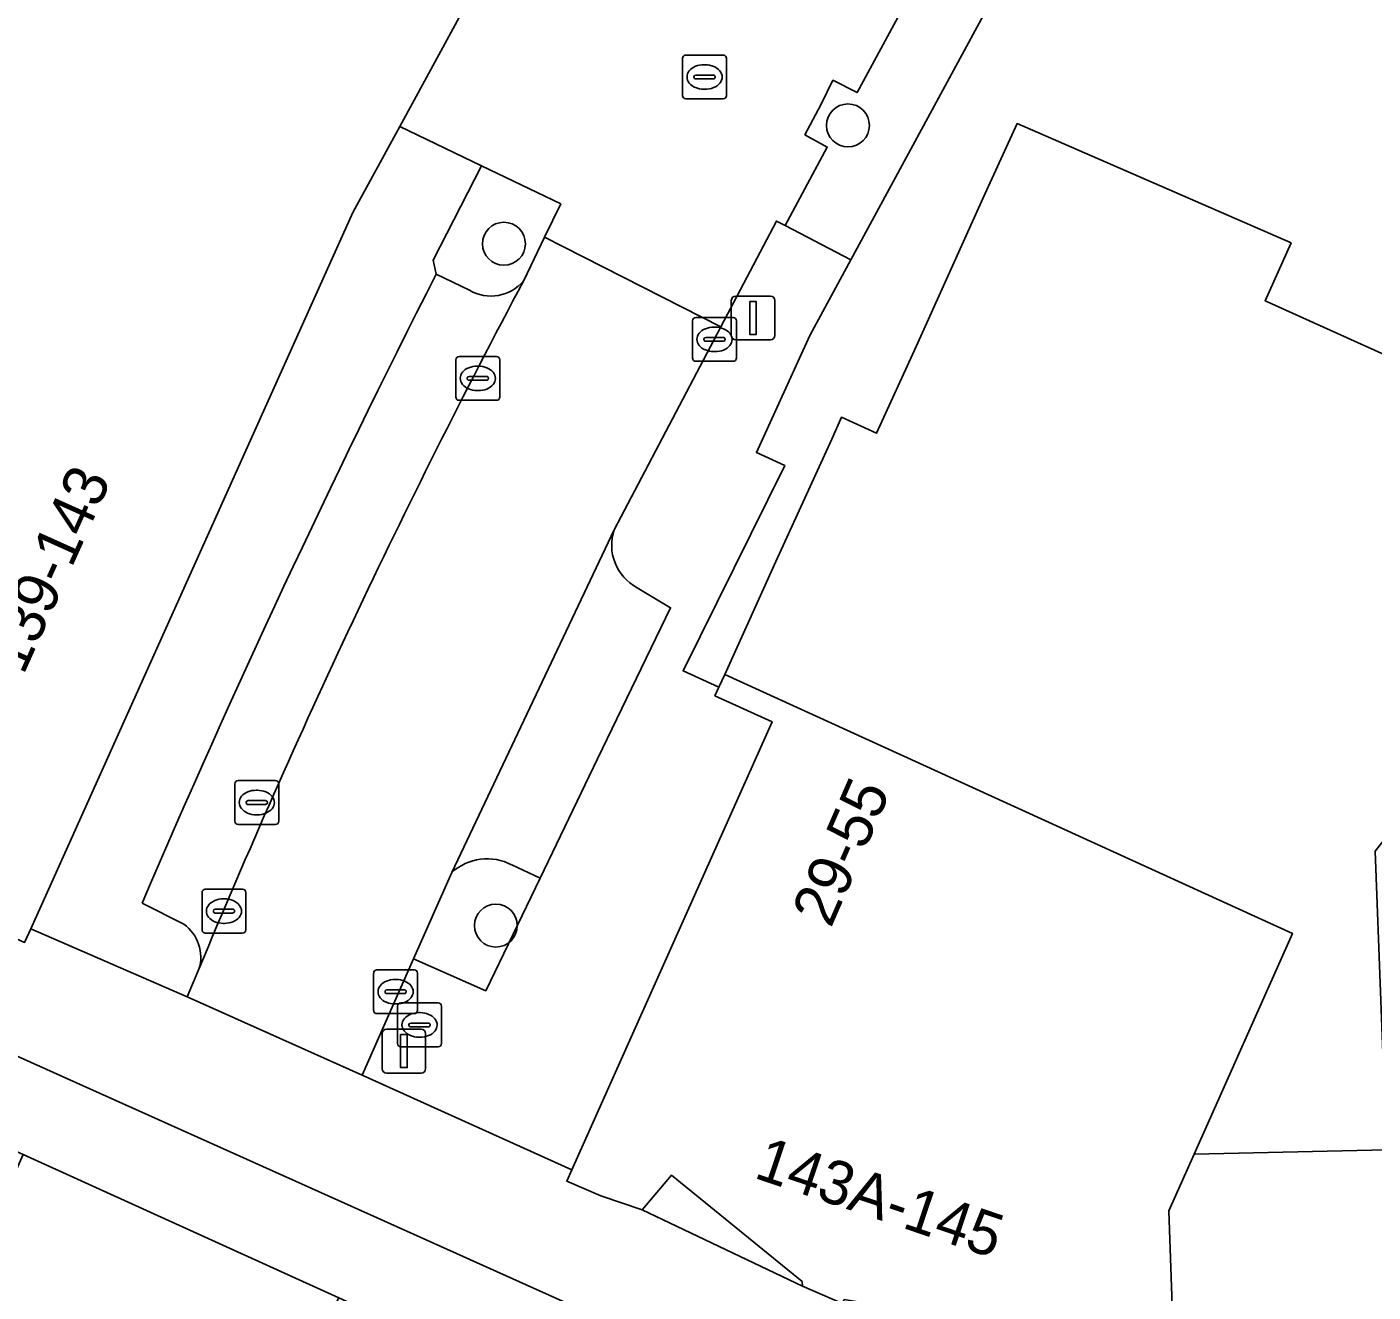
# Model space of a CAD drawing. Extents: x 161881 to 162523, y 381678 to 382381.
# Drawn here: x 162276 to 162306.71, y 381795.21 to 381824.06 of the extents above; entities that cross this region are included whole.
import ezdxf

# ---------------------------------------------------------------- set-up
doc = ezdxf.new("R2010")
doc.units = 0
for name, color, linetype in [('IMGEO_Boom', 7, 'Continuous'), ('IMGEO_Brandkraan', 7, 'Continuous'), ('IMGEO_Erf', 7, 'Continuous'), ('IMGEO_Fietspad_open', 7, 'Continuous'), ('IMGEO_Groenvoorziening', 7, 'Continuous'), ('IMGEO_Kolk', 7, 'Continuous'), ('IMGEO_Lichtmast', 7, 'Continuous'), ('IMGEO_Muur', 7, 'Continuous'), ('IMGEO_Pand', 7, 'Continuous'), ('IMGEO_Pand_nummerreeks', 7, 'Continuous'), ('IMGEO_Pand_overbouw', 7, 'Continuous'), ('IMGEO_Parkeervlak_open', 7, 'Continuous'), ('IMGEO_Rijbaan_lokaal_open', 7, 'Continuous'), ('IMGEO_Rioolput', 7, 'Continuous'), ('IMGEO_Voetpad_open', 7, 'Continuous')]:
    doc.layers.add(name, color=color, linetype=linetype)

msp = doc.modelspace()

# ---------------------------------------------------------------- linework, layer by layer
at = {"layer": 'IMGEO_Boom'}
for centre in [(162294.732, 381821.812), (162286.885, 381819.113), (162286.7, 381803.568)]:
    msp.add_circle(centre, 0.489, dxfattribs=at)
at = {"layer": 'IMGEO_Brandkraan'}
for p, q in [((162284.534, 381801.804), (162285.386, 381801.804)), ((162284.459, 381800.878), (162284.459, 381801.73)), ((162284.947, 381801.584), (162284.972, 381801.584)), ((162285.46, 381801.73), (162285.46, 381800.878)), ((162284.718, 381801.298), (162284.718, 381801.31)), ((162285.156, 381801.261), (162284.758, 381801.261)), ((162284.761, 381801.347), (162285.159, 381801.347)), ((162285.202, 381801.31), (162285.202, 381801.298)), ((162284.97, 381801.024), (162284.945, 381801.024)), ((162285.386, 381800.804), (162284.534, 381800.804))]:
    msp.add_line(p, q, dxfattribs=at)
for points in [[(162284.534, 381801.804), (162285.386, 381801.804)], [(162284.459, 381800.878), (162284.459, 381801.73)], [(162285.46, 381801.73), (162285.46, 381800.878)], [(162285.386, 381800.804), (162284.534, 381800.804)]]:
    msp.add_lwpolyline(points, dxfattribs=at)
for centre, radius, start, end in [((162284.536, 381801.728), 0.0765, 91.552, 178.448), ((162284.536, 381801.728), 0.0765, 91.552, 178.448), ((162285.384, 381801.728), 0.0765, 1.552, 88.448), ((162285.384, 381801.728), 0.0765, 1.552, 88.448), ((162284.758, 381801.307), 0.0403, 85.8775, 175.7526), ((162284.755, 381801.297), 0.0366, 178.938, 274.7102), ((162285.159, 381801.304), 0.043, 264.8664, 352.4533), ((162285.163, 381801.309), 0.0386, 1.7309, 96.639), ((162284.536, 381800.88), 0.0765, 181.552, 268.448), ((162284.536, 381800.88), 0.0765, 181.552, 268.448), ((162285.384, 381800.88), 0.0765, 271.552, 358.448), ((162285.384, 381800.88), 0.0765, 271.552, 358.448)]:
    msp.add_arc(centre, radius, start, end, dxfattribs=at)
for centre, major_axis, ratio, start_param, end_param in [((162284.946, 381801.304), (-0.387, 0.002), 0.722429, 4.712389, 7.853982), ((162284.971, 381801.304), (-0.39, 0.002), 0.717154, 1.570796, 4.712389)]:
    msp.add_ellipse(centre, major_axis=major_axis, ratio=ratio, start_param=start_param, end_param=end_param, dxfattribs=at)
at = {"layer": 'IMGEO_Erf'}
msp.add_lwpolyline([(162298.019, 381824.698), (162294.798, 381818.75), (162293.862, 381817.021), (162292.645, 381814.351), (162293.291, 381814.057), (162290.971, 381809.378), (162291.787, 381809.002), (162291.922, 381809.295), (162304.869, 381803.389), (162302.627, 381798.355), (162307.012, 381798.453), (162306.757, 381805.265), (162309.346, 381808.536), (162307.367, 381809.37), (162312.728, 381813.757), (162316.499, 381816.842), (162317.335, 381817.512), (162321.737, 381821.065), (162323.239, 381822.253), (162321.148, 381824.898)], dxfattribs=at)
at = {"layer": 'IMGEO_Fietspad_open'}
for points in [[(162297.281, 381790.934), (162283.991, 381796.906), (162276.913, 381800.086), (162237.824, 381817.651), (162177.947, 381844.935)], [(162183.799, 381840.053), (162184.069, 381839.866), (162192.812, 381833.805), (162194.089, 381833.367), (162198.754, 381831.251), (162197.694, 381828.855), (162197.222, 381827.799), (162199.963, 381826.58), (162201.558, 381830.008), (162248.9, 381808.653), (162250.093, 381808.023), (162257.97, 381806.387), (162264.876, 381803.292), (162275.916, 381798.35), (162283.117, 381795.079), (162296.058, 381789.157)]]:
    msp.add_lwpolyline(points, dxfattribs=at)
at = {"layer": 'IMGEO_Groenvoorziening'}
msp.add_lwpolyline([(162300.971, 381829.755), (162299.458, 381830.76), (162297.547, 381827.377), (162294.938, 381822.561), (162294.387, 381822.839), (162294.119, 381822.297), (162293.749, 381821.597), (162294.258, 381821.315), (162293.302, 381819.526), (162294.798, 381818.75), (162298.019, 381824.698)], close=True, dxfattribs=at)
for points in [[(162288.18, 381820.023), (162286.375, 381820.89), (162285.269, 381818.741), (162285.34, 381818.419), (162286.097, 381818.054)], [(162287.336, 381818.273), (162287.813, 381819.263), (162288.18, 381820.023)], [(162287.708, 381804.647), (162287.061, 381804.952)], [(162285.695, 381804.778), (162284.825, 381802.812), (162286.47, 381802.083), (162287.708, 381804.647)]]:
    msp.add_lwpolyline(points, dxfattribs=at)
for centre, radius, start, end in [((162286.588, 381818.892), 0.971, 239.6525, 320.3951), ((162286.5, 381803.905), 1.187, 61.8186, 132.6998)]:
    msp.add_arc(centre, radius, start, end, dxfattribs=at)
at = {"layer": 'IMGEO_Kolk'}
for p, q in [((162290.96, 381822.489), (162290.96, 381823.341)), ((162291.035, 381823.415), (162291.887, 381823.415)), ((162291.961, 381823.341), (162291.961, 381822.489)), ((162291.448, 381823.195), (162291.473, 381823.195)), ((162291.219, 381822.909), (162291.219, 381822.921)), ((162291.657, 381822.872), (162291.259, 381822.872)), ((162291.262, 381822.958), (162291.66, 381822.958)), ((162291.703, 381822.921), (162291.703, 381822.909)), ((162291.887, 381822.415), (162291.035, 381822.415)), ((162291.471, 381822.635), (162291.446, 381822.635)), ((162291.187, 381816.507), (162291.187, 381817.359)), ((162291.262, 381817.433), (162292.114, 381817.433)), ((162291.675, 381817.213), (162291.7, 381817.213)), ((162292.188, 381817.359), (162292.188, 381816.507)), ((162291.446, 381816.927), (162291.446, 381816.939)), ((162291.884, 381816.89), (162291.486, 381816.89)), ((162291.489, 381816.976), (162291.887, 381816.976)), ((162291.93, 381816.939), (162291.93, 381816.927)), ((162285.862, 381816.544), (162286.714, 381816.544)), ((162291.698, 381816.653), (162291.673, 381816.653)), ((162285.787, 381815.618), (162285.787, 381816.47)), ((162286.275, 381816.324), (162286.3, 381816.324)), ((162286.788, 381816.47), (162286.788, 381815.618)), ((162292.114, 381816.433), (162291.262, 381816.433)), ((162286.046, 381816.038), (162286.046, 381816.05)), ((162286.484, 381816.001), (162286.086, 381816.001)), ((162286.089, 381816.087), (162286.487, 381816.087)), ((162286.53, 381816.05), (162286.53, 381816.038)), ((162286.298, 381815.764), (162286.273, 381815.764)), ((162286.714, 381815.544), (162285.862, 381815.544)), ((162279.998, 381803.472), (162279.998, 381804.324)), ((162280.073, 381804.398), (162280.925, 381804.398)), ((162280.999, 381804.324), (162280.999, 381803.472)), ((162280.3, 381803.941), (162280.698, 381803.941)), ((162280.486, 381804.178), (162280.511, 381804.178)), ((162280.257, 381803.892), (162280.257, 381803.904)), ((162280.695, 381803.855), (162280.297, 381803.855)), ((162280.741, 381803.904), (162280.741, 381803.892)), ((162280.925, 381803.398), (162280.073, 381803.398)), ((162280.509, 381803.618), (162280.484, 381803.618)), ((162283.913, 381801.635), (162283.913, 381802.487)), ((162283.988, 381802.561), (162284.84, 381802.561)), ((162284.914, 381802.487), (162284.914, 381801.635)), ((162284.215, 381802.104), (162284.613, 381802.104)), ((162284.401, 381802.341), (162284.426, 381802.341)), ((162284.172, 381802.055), (162284.172, 381802.067)), ((162284.61, 381802.018), (162284.212, 381802.018)), ((162284.656, 381802.067), (162284.656, 381802.055)), ((162284.84, 381801.561), (162283.988, 381801.561)), ((162284.424, 381801.781), (162284.399, 381801.781))]:
    msp.add_line(p, q, dxfattribs=at)
for points in [[(162290.96, 381822.489), (162290.96, 381823.341)], [(162291.035, 381823.415), (162291.887, 381823.415)], [(162291.961, 381823.341), (162291.961, 381822.489)], [(162291.887, 381822.415), (162291.035, 381822.415)], [(162291.187, 381816.507), (162291.187, 381817.359)], [(162291.262, 381817.433), (162292.114, 381817.433)], [(162292.188, 381817.359), (162292.188, 381816.507)], [(162285.862, 381816.544), (162286.714, 381816.544)], [(162285.787, 381815.618), (162285.787, 381816.47)], [(162286.788, 381816.47), (162286.788, 381815.618)], [(162292.114, 381816.433), (162291.262, 381816.433)], [(162286.714, 381815.544), (162285.862, 381815.544)], [(162279.998, 381803.472), (162279.998, 381804.324)], [(162280.073, 381804.398), (162280.925, 381804.398)], [(162280.999, 381804.324), (162280.999, 381803.472)], [(162280.925, 381803.398), (162280.073, 381803.398)], [(162283.913, 381801.635), (162283.913, 381802.487)], [(162283.988, 381802.561), (162284.84, 381802.561)], [(162284.914, 381802.487), (162284.914, 381801.635)], [(162284.84, 381801.561), (162283.988, 381801.561)]]:
    msp.add_lwpolyline(points, dxfattribs=at)
for centre, radius, start, end in [((162291.037, 381823.339), 0.0765, 91.552, 178.448), ((162291.037, 381823.339), 0.0765, 91.552, 178.448), ((162291.885, 381823.339), 0.0765, 1.552, 88.448), ((162291.885, 381823.339), 0.0765, 1.552, 88.448), ((162291.259, 381822.918), 0.0403, 85.8775, 175.7526), ((162291.256, 381822.908), 0.0366, 178.938, 274.7102), ((162291.66, 381822.915), 0.043, 264.8664, 352.4533), ((162291.664, 381822.92), 0.0386, 1.7309, 96.639), ((162291.037, 381822.491), 0.0765, 181.552, 268.448), ((162291.037, 381822.491), 0.0765, 181.552, 268.448), ((162291.885, 381822.491), 0.0765, 271.552, 358.448), ((162291.885, 381822.491), 0.0765, 271.552, 358.448), ((162291.264, 381817.357), 0.0765, 91.552, 178.448), ((162291.264, 381817.357), 0.0765, 91.552, 178.448), ((162292.112, 381817.357), 0.0765, 1.552, 88.448), ((162292.112, 381817.357), 0.0765, 1.552, 88.448), ((162291.486, 381816.936), 0.0403, 85.8775, 175.7526), ((162291.483, 381816.926), 0.0366, 178.938, 274.7102), ((162291.887, 381816.933), 0.043, 264.8664, 352.4533), ((162291.891, 381816.938), 0.0386, 1.7309, 96.639), ((162285.864, 381816.468), 0.0765, 91.552, 178.448), ((162285.864, 381816.468), 0.0765, 91.552, 178.448), ((162286.712, 381816.468), 0.0765, 1.552, 88.448), ((162286.712, 381816.468), 0.0765, 1.552, 88.448), ((162291.264, 381816.509), 0.0765, 181.552, 268.448), ((162291.264, 381816.509), 0.0765, 181.552, 268.448), ((162292.112, 381816.509), 0.0765, 271.552, 358.448), ((162292.112, 381816.509), 0.0765, 271.552, 358.448), ((162286.086, 381816.047), 0.0403, 85.8775, 175.7526), ((162286.083, 381816.037), 0.0366, 178.938, 274.7102), ((162286.487, 381816.044), 0.043, 264.8664, 352.4533), ((162286.491, 381816.049), 0.0386, 1.7309, 96.639), ((162285.864, 381815.62), 0.0765, 181.552, 268.448), ((162285.864, 381815.62), 0.0765, 181.552, 268.448), ((162286.712, 381815.62), 0.0765, 271.552, 358.448), ((162286.712, 381815.62), 0.0765, 271.552, 358.448), ((162280.075, 381804.322), 0.0765, 91.552, 178.448), ((162280.075, 381804.322), 0.0765, 91.552, 178.448), ((162280.923, 381804.322), 0.0765, 1.552, 88.448), ((162280.923, 381804.322), 0.0765, 1.552, 88.448), ((162280.297, 381803.901), 0.0403, 85.8775, 175.7526), ((162280.702, 381803.903), 0.0386, 1.7309, 96.639), ((162280.294, 381803.891), 0.0366, 178.938, 274.7102), ((162280.698, 381803.898), 0.043, 264.8664, 352.4533), ((162280.075, 381803.474), 0.0765, 181.552, 268.448), ((162280.075, 381803.474), 0.0765, 181.552, 268.448), ((162280.923, 381803.474), 0.0765, 271.552, 358.448), ((162280.923, 381803.474), 0.0765, 271.552, 358.448), ((162283.99, 381802.485), 0.0765, 91.552, 178.448), ((162283.99, 381802.485), 0.0765, 91.552, 178.448), ((162284.838, 381802.485), 0.0765, 1.552, 88.448), ((162284.838, 381802.485), 0.0765, 1.552, 88.448), ((162284.212, 381802.064), 0.0403, 85.8775, 175.7526), ((162284.617, 381802.066), 0.0386, 1.7309, 96.639), ((162284.209, 381802.054), 0.0366, 178.938, 274.7102), ((162284.613, 381802.061), 0.043, 264.8664, 352.4533), ((162283.99, 381801.637), 0.0765, 181.552, 268.448), ((162283.99, 381801.637), 0.0765, 181.552, 268.448), ((162284.838, 381801.637), 0.0765, 271.552, 358.448), ((162284.838, 381801.637), 0.0765, 271.552, 358.448)]:
    msp.add_arc(centre, radius, start, end, dxfattribs=at)
for centre, major_axis, ratio, start_param, end_param in [((162291.447, 381822.915), (-0.387, 0.002), 0.722429, 4.712389, 7.853982), ((162291.472, 381822.915), (-0.39, 0.002), 0.717154, 1.570796, 4.712389), ((162291.674, 381816.933), (-0.387, 0.002), 0.722429, 4.712389, 7.853982), ((162291.699, 381816.933), (-0.39, 0.002), 0.717154, 1.570796, 4.712389), ((162286.274, 381816.044), (-0.387, 0.002), 0.722429, 4.712389, 7.853982), ((162286.299, 381816.044), (-0.39, 0.002), 0.717154, 1.570796, 4.712389), ((162280.485, 381803.898), (-0.387, 0.002), 0.722429, 4.712389, 7.853982), ((162280.51, 381803.898), (-0.39, 0.002), 0.717154, 1.570796, 4.712389), ((162284.4, 381802.061), (-0.387, 0.002), 0.722429, 4.712389, 7.853982), ((162284.425, 381802.061), (-0.39, 0.002), 0.717154, 1.570796, 4.712389)]:
    msp.add_ellipse(centre, major_axis=major_axis, ratio=ratio, start_param=start_param, end_param=end_param, dxfattribs=at)
at = {"layer": 'IMGEO_Lichtmast'}
for p, q in [((162292.071, 381817.021), (162292.071, 381817.821)), ((162292.071, 381817.821), (162292.071, 381817.021)), ((162292.171, 381817.921), (162292.961, 381817.921)), ((162292.961, 381817.921), (162292.171, 381817.921)), ((162293.061, 381817.821), (162293.061, 381817.021)), ((162293.061, 381817.021), (162293.061, 381817.821)), ((162292.961, 381816.921), (162292.171, 381816.921)), ((162292.171, 381816.921), (162292.961, 381816.921)), ((162284.209, 381801.207), (162284.999, 381801.207)), ((162284.999, 381801.207), (162284.209, 381801.207)), ((162284.109, 381800.307), (162284.109, 381801.107)), ((162284.109, 381801.107), (162284.109, 381800.307)), ((162285.099, 381801.107), (162285.099, 381800.307)), ((162285.099, 381800.307), (162285.099, 381801.107)), ((162284.999, 381800.207), (162284.209, 381800.207)), ((162284.209, 381800.207), (162284.999, 381800.207))]:
    msp.add_line(p, q, dxfattribs=at)
for points in [[(162292.491, 381817.796), (162292.641, 381817.796), (162292.641, 381817.046), (162292.491, 381817.046), (162292.491, 381817.796)], [(162284.529, 381801.082), (162284.679, 381801.082), (162284.679, 381800.332), (162284.529, 381800.332), (162284.529, 381801.082)]]:
    msp.add_lwpolyline(points, dxfattribs=at)
for centre, start, end in [((162292.171, 381817.821), 90, 180), ((162292.171, 381817.821), 90, 180), ((162292.961, 381817.821), 0, 90), ((162292.961, 381817.821), 360, 90), ((162292.171, 381817.021), 180, 270), ((162292.171, 381817.021), 180, 270), ((162292.961, 381817.021), 270, 0), ((162292.961, 381817.021), 270, 0), ((162284.209, 381801.107), 90, 180), ((162284.209, 381801.107), 90, 180), ((162284.999, 381801.107), 0, 90), ((162284.999, 381801.107), 360, 90), ((162284.209, 381800.307), 180, 270), ((162284.209, 381800.307), 180, 270), ((162284.999, 381800.307), 270, 0), ((162284.999, 381800.307), 270, 0)]:
    msp.add_arc(centre, 0.1, start, end, dxfattribs=at)
at = {"layer": 'IMGEO_Muur'}
msp.add_lwpolyline([(162302.232, 381831.916), (162300.971, 381829.755), (162298.019, 381824.698), (162294.798, 381818.75), (162293.862, 381817.021), (162292.645, 381814.351), (162293.291, 381814.057)], dxfattribs=at)
at = {"layer": 'IMGEO_Pand'}
for points in [[(162284.507, 381821.787), (162288.539, 381829.192), (162283.992, 381831.27), (162279.396, 381833.371), (162279.176, 381832.887), (162277.263, 381833.76), (162278.028, 381835.435), (162273.937, 381837.352), (162273.499, 381836.351), (162273.867, 381836.183), (162272.302, 381832.759), (162271.987, 381832.903), (162269.766, 381827.834), (162270.107, 381827.678), (162269.172, 381825.632), (162274.569, 381822.855), (162270.405, 381813.427), (162267.49, 381807.052), (162275.953, 381803.185), (162276.093, 381803.496), (162283.439, 381819.827)], [(162302.627, 381798.355), (162304.869, 381803.389), (162291.922, 381809.295), (162291.787, 381809.002), (162291.697, 381808.807), (162292.999, 381808.217), (162288.433, 381798), (162288.319, 381797.745), (162289.094, 381797.411), (162290.041, 381797.092), (162290.703, 381797.878), (162293.689, 381795.454), (162293.697, 381795.348), (162294.606, 381794.949), (162294.648, 381795.043), (162298.424, 381794.415), (162298.311, 381793.408), (162299.215, 381792.988), (162299.197, 381792.879), (162299.946, 381792.55), (162300.431, 381793.533), (162302.174, 381793.607), (162302.053, 381797.066)]]:
    msp.add_lwpolyline(points, close=True, dxfattribs=at)
at = {"layer": 'IMGEO_Pand_overbouw'}
for points in [[(162311.657, 381814.468), (162304.248, 381817.81), (162304.839, 381819.133), (162298.588, 381821.853), (162297.818, 381820.158), (162296.287, 381816.77), (162295.385, 381814.794), (162294.582, 381815.156), (162294.362, 381814.66), (162293.088, 381811.866), (162291.922, 381809.295), (162304.869, 381803.389), (162302.627, 381798.355), (162307.012, 381798.453), (162306.757, 381805.265), (162309.346, 381808.536), (162307.367, 381809.37), (162307.195, 381809.443)], [(162290.041, 381797.092), (162293.697, 381795.348), (162293.689, 381795.454), (162290.703, 381797.878)]]:
    msp.add_lwpolyline(points, close=True, dxfattribs=at)
at = {"layer": 'IMGEO_Parkeervlak_open'}
for points in [[(162286.097, 381818.054), (162285.34, 381818.419)], [(162289.401, 381812.594), (162285.695, 381804.778)], [(162290.685, 381810.815), (162289.924, 381811.272)], [(162287.061, 381804.952), (162287.708, 381804.647), (162289.021, 381807.367), (162290.685, 381810.815)], [(162278.63, 381804.076), (162279.583, 381803.599)]]:
    msp.add_lwpolyline(points, dxfattribs=at)
for centre, radius, start, end in [((162498.164, 381710.114), 238.797, 153.02865, 156.82871), ((162445.875, 381733.874), 179.605, 151.97103, 157.51149), ((162286.588, 381818.892), 0.971, 239.6525, 320.3951), ((162290.437, 381812.239), 1.095, 161.0977, 242.071), ((162286.5, 381803.905), 1.187, 61.8186, 132.6998), ((162279.042, 381802.846), 0.928, 342.8431, 54.2944)]:
    msp.add_arc(centre, radius, start, end, dxfattribs=at)
at = {"layer": 'IMGEO_Rijbaan_lokaal_open'}
for points in [[(162288.539, 381829.192), (162284.507, 381821.787), (162286.375, 381820.89), (162288.18, 381820.023), (162287.813, 381819.263), (162291.833, 381817.222), (162293.099, 381819.631), (162293.302, 381819.526), (162294.258, 381821.315), (162293.749, 381821.597), (162294.119, 381822.297), (162294.387, 381822.839), (162294.938, 381822.561), (162297.547, 381827.377)], [(162289.401, 381812.594), (162291.833, 381817.222), (162287.813, 381819.263), (162287.336, 381818.273)], [(162279.928, 381802.572), (162279.658, 381801.942), (162283.648, 381800.155), (162284.825, 381802.812), (162285.695, 381804.778), (162289.401, 381812.594)]]:
    msp.add_lwpolyline(points, dxfattribs=at)
msp.add_lwpolyline([(162275.916, 381798.35), (162275.238, 381796.831), (162273.07, 381797.83), (162272.193, 381795.887), (162271.685, 381794.828), (162275.604, 381793.251), (162278.827, 381791.782), (162282.603, 381789.888), (162283.177, 381790.863), (162281.429, 381791.791), (162281.822, 381792.572), (162283.117, 381795.079)], close=True, dxfattribs=at)
msp.add_arc((162445.875, 381733.874), 179.605, 151.97103, 157.51149, dxfattribs=at)
at = {"layer": 'IMGEO_Rioolput'}
for p, q in [((162280.747, 381805.948), (162280.747, 381806.8)), ((162280.822, 381806.874), (162281.674, 381806.874)), ((162281.748, 381806.8), (162281.748, 381805.948)), ((162281.049, 381806.417), (162281.447, 381806.417)), ((162281.235, 381806.654), (162281.26, 381806.654)), ((162281.006, 381806.368), (162281.006, 381806.38)), ((162281.444, 381806.331), (162281.046, 381806.331)), ((162281.258, 381806.094), (162281.233, 381806.094)), ((162281.49, 381806.38), (162281.49, 381806.368)), ((162281.674, 381805.874), (162280.822, 381805.874))]:
    msp.add_line(p, q, dxfattribs=at)
for points in [[(162280.747, 381805.948), (162280.747, 381806.8)], [(162280.822, 381806.874), (162281.674, 381806.874)], [(162281.748, 381806.8), (162281.748, 381805.948)], [(162281.674, 381805.874), (162280.822, 381805.874)]]:
    msp.add_lwpolyline(points, dxfattribs=at)
for centre, radius, start, end in [((162280.824, 381806.798), 0.0765, 91.552, 178.448), ((162280.824, 381806.798), 0.0765, 91.552, 178.448), ((162281.672, 381806.798), 0.0765, 1.552, 88.448), ((162281.672, 381806.798), 0.0765, 1.552, 88.448), ((162281.046, 381806.377), 0.0403, 85.8775, 175.7526), ((162281.451, 381806.379), 0.0386, 1.7309, 96.639), ((162281.043, 381806.367), 0.0366, 178.938, 274.7102), ((162281.447, 381806.374), 0.043, 264.8664, 352.4533), ((162280.824, 381805.95), 0.0765, 181.552, 268.448), ((162280.824, 381805.95), 0.0765, 181.552, 268.448), ((162281.672, 381805.95), 0.0765, 271.552, 358.448), ((162281.672, 381805.95), 0.0765, 271.552, 358.448)]:
    msp.add_arc(centre, radius, start, end, dxfattribs=at)
for centre, major_axis, ratio, start_param, end_param in [((162281.234, 381806.374), (-0.387, 0.002), 0.722429, 4.712389, 7.853982), ((162281.259, 381806.374), (-0.39, 0.002), 0.717154, 1.570796, 4.712389)]:
    msp.add_ellipse(centre, major_axis=major_axis, ratio=ratio, start_param=start_param, end_param=end_param, dxfattribs=at)
at = {"layer": 'IMGEO_Voetpad_open'}
for points in [[(162177.947, 381844.935), (162237.824, 381817.651), (162276.913, 381800.086), (162283.991, 381796.906), (162297.281, 381790.934)], [(162285.34, 381818.419), (162285.269, 381818.741), (162286.375, 381820.89), (162284.507, 381821.787), (162283.439, 381819.827), (162276.093, 381803.496), (162279.658, 381801.942), (162279.928, 381802.572)], [(162291.787, 381809.002), (162290.971, 381809.378), (162293.291, 381814.057), (162292.645, 381814.351), (162293.862, 381817.021), (162294.798, 381818.75), (162293.302, 381819.526), (162293.099, 381819.631), (162291.833, 381817.222), (162289.401, 381812.594)], [(162289.924, 381811.272), (162290.685, 381810.815), (162289.021, 381807.367), (162287.708, 381804.647), (162286.47, 381802.083), (162284.825, 381802.812), (162283.648, 381800.155), (162288.433, 381798), (162292.999, 381808.217), (162291.697, 381808.807), (162291.787, 381809.002)], [(162279.583, 381803.599), (162278.63, 381804.076)], [(162307.012, 381798.453), (162302.627, 381798.355), (162302.053, 381797.066), (162302.174, 381793.607), (162300.431, 381793.533), (162299.946, 381792.55), (162299.197, 381792.879), (162299.215, 381792.988), (162298.311, 381793.408), (162298.424, 381794.415), (162294.648, 381795.043), (162294.606, 381794.949), (162293.697, 381795.348), (162293.689, 381795.454), (162290.703, 381797.878), (162290.041, 381797.092), (162289.094, 381797.411), (162288.319, 381797.745), (162288.433, 381798), (162283.648, 381800.155), (162279.658, 381801.942), (162276.093, 381803.496), (162275.953, 381803.185)]]:
    msp.add_lwpolyline(points, dxfattribs=at)
for centre, radius, start, end in [((162498.164, 381710.114), 238.797, 153.02865, 156.82871), ((162290.437, 381812.239), 1.095, 161.0977, 242.071), ((162279.042, 381802.846), 0.928, 342.8431, 54.2944)]:
    msp.add_arc(centre, radius, start, end, dxfattribs=at)

# ---------------------------------------------------------------- texts
at = {"layer": 'IMGEO_Pand_nummerreeks'}
for s, rotation, p in [('139-143', 65.7813, (162275.922, 381809.26)), ('29-55', 66.4115, (162294.339, 381803.492)), ('143A-145', 341.3846, (162292.559, 381797.827))]:
    msp.add_text(s, height=1, rotation=rotation, dxfattribs=at).set_placement(p)

doc.saveas('drawing.dxf')
